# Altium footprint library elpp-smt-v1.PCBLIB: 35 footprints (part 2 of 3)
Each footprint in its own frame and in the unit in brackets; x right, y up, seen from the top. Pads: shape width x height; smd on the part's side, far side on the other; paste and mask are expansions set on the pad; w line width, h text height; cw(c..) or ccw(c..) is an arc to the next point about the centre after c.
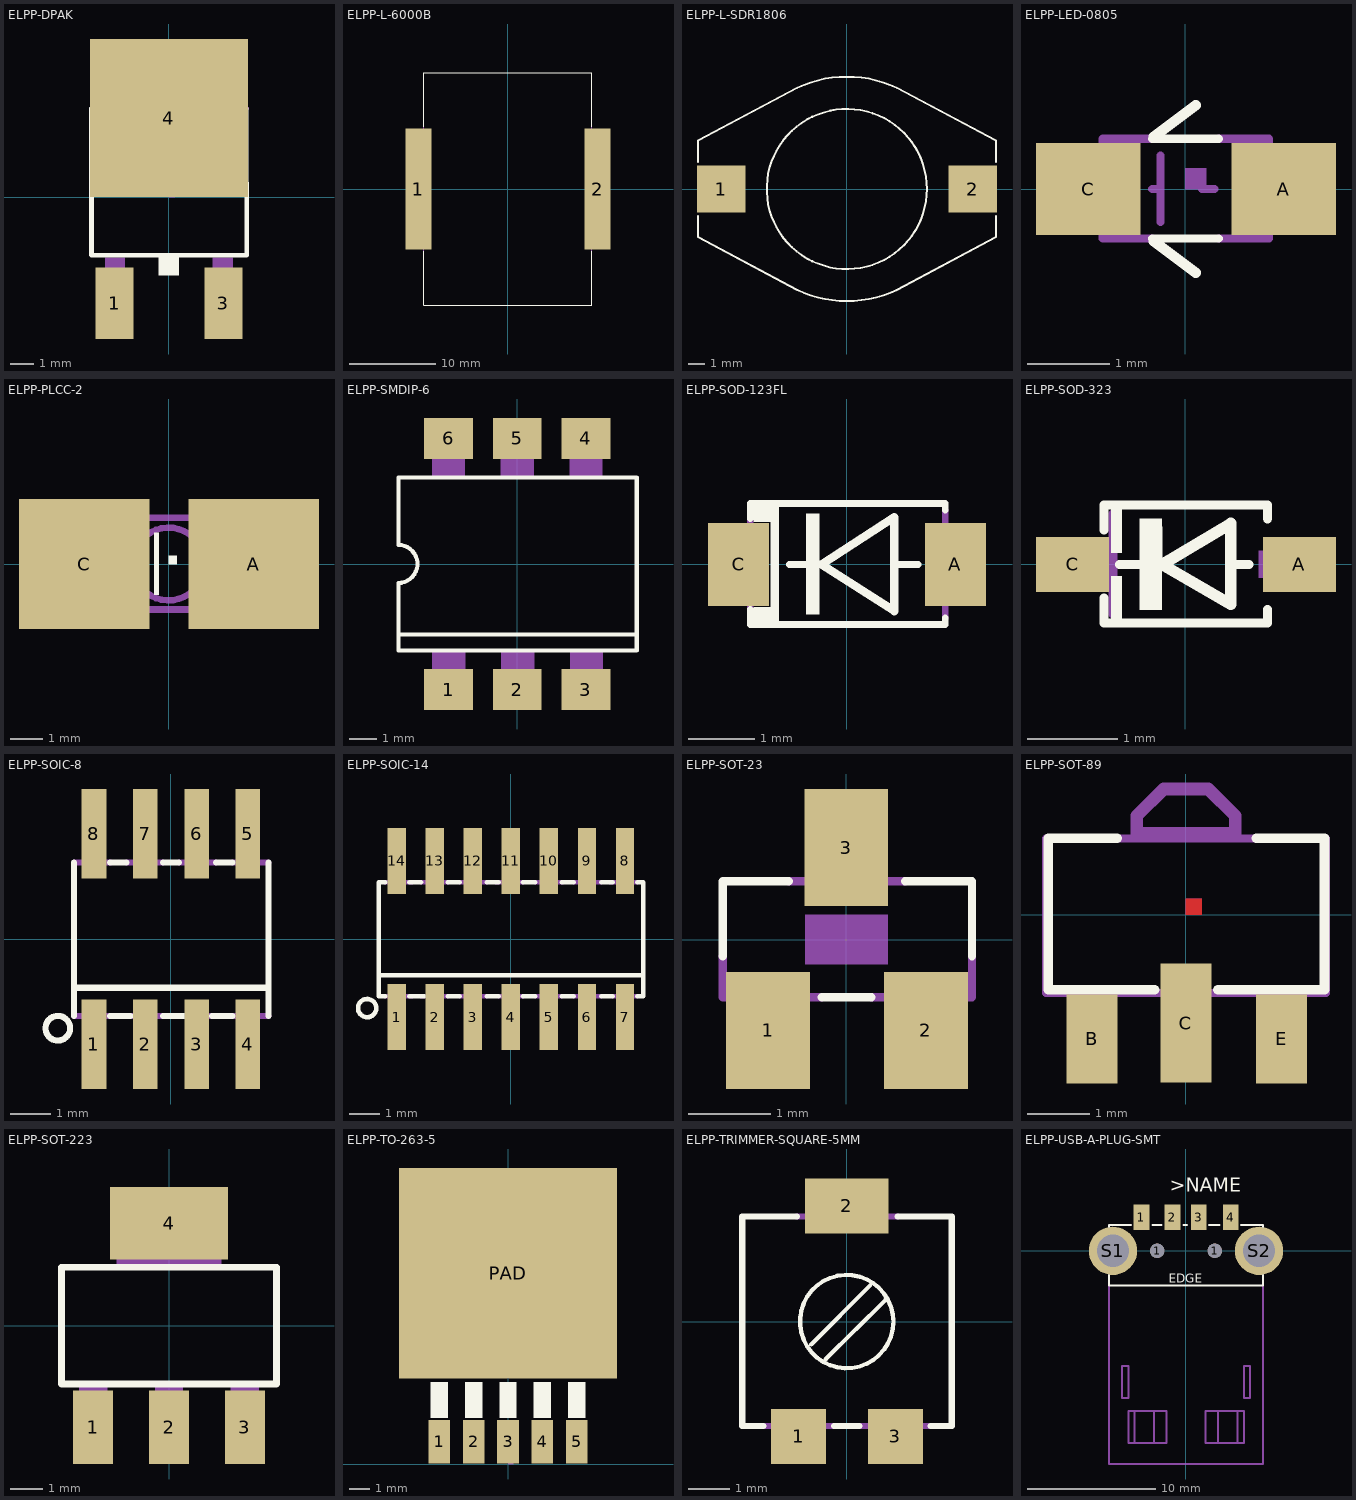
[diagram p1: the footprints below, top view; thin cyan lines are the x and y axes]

## ELPP-DPAK [mil]
pads (3):
  rect 63x119 smd: 1(-90.55,-177.17) 3(91,-177.17)
  rect 264x264 smd: 4(0,132)
Top Overlay:
  rectangle: -17,-130.81 17,-100.81
  lines w8: -129,148 -129.02,-96.81 130,-96.81 129,148
Mechanical 2:
  text ">NAME" at -150,-115.75 h42.5
Mechanical 4:
  text ">VALUE" at 200,-115.75 h42.5
Mechanical 16:
  rectangle: -107,-214.81 -73,-100.81
  rectangle: 73,-214.81 107,-100.81
  region: 0,0 10,0 10,10 0,10
  lines w8: -129.02,148 130,148 ; -101,152 -101,180 -83,198 83,198 101,180 101,152 -101,152

## ELPP-L-6000B [mil]
pads (2):
  rect 119x552 smd: 1(-409.45,0) 2(410,0)
Top Overlay:
  lines w5: -383.86,-283.46 -383.86,-531.5 384,-531.5 384,-283.46 ; -383.86,284 -383.86,532 384,532 384,284
Mechanical 2:
  text ">NAME" at -367.76,546 h42.5
Mechanical 4:
  text ">VALUE" at -364.96,452 h42.5
Mechanical 16:
  lines w5: -383.86,-283.46 -383.86,284 ; 384,-283.46 384,284

## ELPP-L-SDR1806 [mil]
pads (2):
  rect 119x115 smd: 1(-309.06,0) 2(310,0)
Top Overlay:
  circle w5: c0,0 r197
  lines w5: -366.14,-66.93 -366.14,-118.11 -122.05,-248.03 ccw(c-1.71,0.88) 0,-275.59 ccw(c2.29,2.47) 123,-248.03 367,-118.11 367,-66.93 ; -366.14,67 -366.14,119 -122.05,249 cw(c-3.01,0.27) 0,276 cw(c3.39,-2.24) 123,249 367,119 367,67
Mechanical 2:
  text ">NAME" at 243,204 h42.5
Mechanical 4:
  text ">VALUE" at 246,-253.54 h42.5

## ELPP-LED-0805 [mil]
pads (2):
  rect 50x44 smd: A(47,0) C(-46.26,0)
Top Overlay:
  lines w4: -15.75,-23.62 16,-23.62 ; -15.75,24 16,24
  lines w5: -15,-25 5,-40 ; -15,25 5,40
Mechanical 2:
  text ">NAME" at 77,-25.59 h42.5
Mechanical 4:
  text ">VALUE" at -61.02,-92.68 h42.5
Mechanical 16:
  region: 0,0 10,0 10,10 0,10
  lines w4: -15.75,-23.62 -39.37,-23.62 -39.37,24 -15.75,24 ; -15.75,0 -11.81,0 ; -11.81,-15.75 -11.81,0 ; -11.81,16 -11.81,0 ; 8,0 14,0 ; 16,-23.62 40,-23.62 40,24 16,24

## ELPP-PLCC-2 [mil]
pads (2):
  rect 158x158 smd: A(103,0) C(-102.36,0)
Top Overlay:
  rectangle: -17.72,-37.4 -11.81,38
  region: 0,0 10,0 10,10 0,10
Top Paste:
  region: -88.82,51.42 -88.82,-50.94 -29.29,-50.94 -29.29,51.42
  region: 29.74,51.74 29.74,-51.26 89.26,-51.26 89.26,51.74
Top Solder:
  rectangle: 24,-51.18 87,52
  region: -23.62,52 -86.61,52 -86.61,-51.18 -23.62,-51.18
Mechanical 2:
  text ">NAME" at 193,-22.05 h42.5
Mechanical 4:
  text ">VALUE" at -75,-150 h42.5
Mechanical 16:
  circle w8: c0,0 r44
  lines w4: -62.99,-43.31 -70.87,-43.31 -70.87,44 -62.99,44 ; 63,-43.31 71,-43.31 71,44 63,44
  lines w8: -62.99,34 -62.99,44 -62.99,56 -41.34,56 ; -62.99,34 -62.99,-43.31 -62.99,-55.12 63,-55.12 63,-43.31 63,44 63,56 -41.34,56 ; -62.99,34 -41.34,56

## ELPP-SMDIP-6 [mil]
pads (6):
  rect 71x60 smd: 1(-100,-182.87) 2(0,-182.87) 3(100,-182.87) 4(100,183) 5(0,183) 6(-100,183)
Top Overlay:
  lines w6: -173.23,-102.36 -173.23,-125.98 174,-125.98 174,-102.36 ; -173.23,-102.36 -173.23,-27.56 ccw(c-173.23,0.22) -173.23,28 -173.23,126 174,126 174,-102.36 ; -173.23,-102.36 174,-102.36
Mechanical 2:
  text ">NAME" at -200,-125 h42.5
Mechanical 4:
  text ">VALUE" at -114.57,-25 h42.5
Mechanical 16:
  rectangle: -123.82,-194.88 -75.59,-125.98
  rectangle: -23.82,-194.88 25,-125.98
  rectangle: 77,-194.88 125,-125.98
  region: 124,195 76,195 76,126 124,126
  region: 24,195 -24.41,195 -24.41,126 24,126
  region: -76.18,195 -124.41,195 -124.41,126 -76.18,126

## ELPP-SOD-123FL [mil]
pads (2):
  rect 36x49 smd: A(64,0) C(-63.98,0)
Top Overlay:
  rectangle: -24.15,-29.53 -16.28,30
  rectangle: -45,-35 -40,35
  rectangle: -55,25 -45,35
  rectangle: -55,-35 -45,-25
  lines w4: -57.09,-26.5 -57.09,-35.43 -54.59,-35.43 -52.09,-35.43 -49.59,-35.43 -47.09,-35.43 58,-35.43 58,-31.5 ; -57.09,27 -57.09,36 -54.59,36 -52.09,36 -49.59,36 -47.09,36 58,36 58,32 ; -34,0 -15,0 -13.78,0 ; 29,0 42,0
  lines w5: -15,0 28,28 28,-27.5 -15,0
Mechanical 2:
  text ">NAME" at 95,-23.62 h42.5
Mechanical 4:
  text ">VALUE" at -78.74,-98.43 h42.5
Mechanical 16:
  rectangle: -70.87,-21.65 -56.1,22
  region: 71,22 57,22 57,-21.65 71,-21.65
  lines w4: -57.09,-31.5 -57.09,32 ; 58,-31.5 58,32

## ELPP-SOD-323 [mil]
pads (2):
  rect 32x24 smd: A(50,0) C(-49.21,0)
Top Overlay:
  rectangle: -20,-20 -10,20
  rectangle: -32.5,-25 -27.5,-5
  rectangle: -32.5,5 -27.5,25
  lines w4: -35.43,-14.69 -35.43,-25.59 -32.93,-25.59 -30.43,-25.59 -27.93,-25.59 36,-25.59 36,-19.68 ; -35.43,15 -35.43,26 -32.93,26 -30.43,26 -27.93,26 36,26 36,20 ; -28.62,0 -11.81,0 -11.81,16 ; 20,0 28,0
  lines w5: -10,0 20,18 20,-17.5 -10,0
Mechanical 2:
  text ">NAME" at 73,-25.59 h42.5
Mechanical 4:
  text ">VALUE" at -64.96,-86.61 h42.5
Mechanical 16:
  rectangle: -49.21,-5.91 -31.5,6
  rectangle: 32,-5.91 50,6
  lines w4: -31.5,-21.65 -31.5,22

## ELPP-SOIC-8 [mil]
pads (8):
  rect 24x87 smd: 1(-75,-102.36) 2(-25,-102.36) 3(25,-102.36) 4(75,-102.36) 5(75,103) 6(25,103) 7(-25,103) 8(-75,103)
Top Overlay:
  circle w6: c-110.24,-86.61 r12
  lines w6: -94.49,-74.8 -94.49,75 ; -94.49,-47.24 95,-47.24 ; -59.06,-74.8 -39.37,-74.8 ; -59.06,75 -43.31,75 ; -7.87,-74.8 12,-74.8 ; -7.87,75 8,75 ; 40,-74.8 60,-74.8 ; 44,75 60,75 ; 95,-74.8 95,75
Mechanical 2:
  text ">NAME" at -125,-75 h42.5
Mechanical 4:
  text ">VALUE" at 175,-75 h42.5
Mechanical 16:
  rectangle: -84.65,-122.05 -65.35,-78.74
  rectangle: -34.65,-122.05 -15.35,-78.74
  rectangle: 16,-122.05 35,-78.74
  rectangle: 66,-122.05 85,-78.74
  rectangle: 66,79 85,123
  rectangle: 16,79 35,123
  rectangle: -34.65,79 -15.35,123
  rectangle: -84.65,79 -65.35,123
  lines w6: -94.49,-74.8 -59.06,-74.8 ; -94.49,75 -59.06,75 ; -43.31,75 -7.87,75 ; -39.37,-74.8 -7.87,-74.8 ; 8,-74.8 40,-74.8 ; 8,75 44,75 ; 60,-74.8 95,-74.8 ; 60,75 95,75

## ELPP-SOIC-14 [mil]
pads (14):
  rect 24x87 smd: 1(-150,-102.36) 2(-100,-102.36) 3(-50,-102.36) 4(0,-102.36) 5(50,-102.36) 6(100,-102.36) 7(150,-102.36) 8(150,103) 9(100,103) 10(50,103) 11(0,103) 12(-50,103) 13(-100,103) 14(-150,103)
Top Overlay:
  circle w6: c-188.98,-90.55 r12
  lines w6: -173.43,-74.8 -173.43,-47.24 ; -173.43,75 -173.43,-47.24 ; -173.23,-74.8 -165.35,-74.8 ; -173.23,75 -165.35,75 ; -133.86,-74.8 -114.17,-74.8 ; -133.86,75 -118.11,75 ; -82.68,-74.8 -66.93,-74.8 ; -82.68,75 -66.93,75 ; -31.5,-74.8 -15.75,-74.8 ; -31.5,75 -15.75,75 ; 16,-74.8 32,-74.8 ; 16,75 32,75 ; 67,-74.8 83,-74.8 ; 67,75 83,75 ; 119,-74.8 134,-74.8 ; 119,75 134,75 ; 166,-74.8 174,-74.8 174,-47.24 ; 166,75 174,75 174,-47.24 ; -173.43,-47.24 174,-47.24
Mechanical 2:
  text ">NAME" at -200,-75 h42.5
Mechanical 4:
  text ">VALUE" at 250,-75 h42.5
Mechanical 16:
  rectangle: -159.65,-122.05 -140.35,-78.74
  rectangle: -109.65,-122.05 -90.35,-78.74
  rectangle: -59.65,-122.05 -40.35,-78.74
  rectangle: -9.65,-122.05 10,-78.74
  rectangle: -9.65,79 10,123
  rectangle: -59.65,79 -40.35,123
  rectangle: -109.65,79 -90.35,123
  rectangle: -159.65,79 -140.35,123
  rectangle: 41,-122.05 60,-78.74
  rectangle: 91,-122.05 110,-78.74
  rectangle: 141,-122.05 160,-78.74
  rectangle: 141,79 160,123
  rectangle: 91,79 110,123
  rectangle: 41,79 60,123
  lines w6: -165.55,-74.8 -129.72,-74.8 ; -165.55,75 -129.72,75 ; -118.31,75 -82.48,75 ; -118.11,-74.8 -82.68,-74.8 ; -67.13,75 -31.3,75 ; -66.93,-74.8 -31.5,-74.8 ; -19.88,75 16,75 ; -15.75,-74.8 16,-74.8 ; 32,-74.8 67,-74.8 ; 32,75 68,75 ; 83,-74.8 119,-74.8 ; 83,75 119,75 ; 130,75 166,75 ; 134,-74.8 166,-74.8

## ELPP-SOT-23 [mil]
pads (3):
  rect 40x56 smd: 1(-37.4,-43.31) 2(38,-43.31) 3(0,44)
Top Overlay:
  lines w4: -59.06,-7.87 -59.06,28 -27.56,28 ; -11.81,-27.56 12,-27.56 ; 28,28 60,28 60,-7.87
Mechanical 2:
  text ">NAME" at 71,-23.43 h42.5
Mechanical 4:
  text ">VALUE" at 71,-81.69 h42.5
Mechanical 6:
  rectangle: -19.69,-11.81 20,12
Mechanical 16:
  rectangle: -9,28 9,51
  rectangle: 28,-51 46,-28
  rectangle: -46,-51 -28,-28
  lines w4: -59.06,-7.87 -59.06,-27.56 -11.81,-27.56 ; -27.56,28 28,28 ; 12,-27.56 60,-27.56 60,-7.87

## ELPP-SOT-89 [mil]
pads (3):
  rect 32x56 smd: B(-59.02,-77.99) E(60,-77.99)
  rect 32x75 smd: C(0,-67.99)
Top Layer:
  region: 0,0 10,0 10,10 0,10
Top Overlay:
  lines w6: -43.31,48 -86.61,48 -86.61,-47.24 -19.68,-47.24 ; 20,-47.24 87,-47.24 87,48 44,48
Top Paste:
  rectangle: -15.75,-105.51 16,-50.39
  region: 0,0 10,0 10,10 0,10
Top Solder:
  rectangle: -19.68,-109.45 20,-46.46
  region: 0,0 10,0 10,10 0,10
Mechanical 2:
  text ">NAME" at -56.69,129 h42.5
Mechanical 4:
  text ">VALUE" at -94.69,-171.06 h42.5
Mechanical 16:
  rectangle: -68,-83 -50,-50
  rectangle: 50,-83 68,-50
  rectangle: -11,-83 11,-50
  region: 0,0 10,0 10,10 0,10
  lines w5: -87.99,-49.02 88,-49.02 88,48 -87.99,48 -87.99,-49.02
  lines w8: -31,51 31,51 31,62 14,79 -14,79 -31,62 -31,51

## ELPP-SOT-223 [mil]
pads (4):
  rect 48x88 smd: 1(-91,-122) 2(0,-122) 3(91,-122)
  rect 142x87 smd: 4(0,123)
Top Overlay:
  lines w8: -129,-70 129,-70 129,70 -129,70 -129,-70
Mechanical 2:
  text ">NAME" at -64.57,176 h42.5
Mechanical 4:
  text ">VALUE" at 198,-155.12 h42.5
Mechanical 16:
  rectangle: -63,71 63,144
  rectangle: -17,-144 17,-71
  rectangle: -108,-144 -74,-71
  rectangle: 74,-144 108,-71
  rectangle: -63,71 63,144
  rectangle: -17,-144 17,-71
  rectangle: -108,-144 -74,-71
  rectangle: 74,-144 108,-71

## ELPP-TO-263-5 [mil]
pads (6):
  rect 42x85 smd: 1(-134,43) 2(-67,43) 3(0,43) 4(67,43) 5(134,43)
  rect 425x410 smd: PAD(0,372)
Top Overlay:
  rectangle: -17,90 17,160
  rectangle: 50,90 84,160
  rectangle: 117,90 151,160
  rectangle: -84,90 -50,160
  rectangle: -151,90 -117,160
Mechanical 2:
  text ">NAME" at -105.75,592 h42.5
Mechanical 4:
  text ">VALUE" at 277,170 h42.5
Mechanical 16:
  region: 0,0 10,0 10,10 0,10
  lines w8: -200,175 200,175 200,515 -200,515 -200,175 ; -196,517 -196,545 -178,563 178,563 196,545 196,517 -196,517

## ELPP-TRIMMER-SQUARE-5MM [mil]
pads (3):
  rect 52x52 smd: 1(-45.28,-108.27) 3(46,-108.27)
  rect 79x52 smd: 2(0,109)
Top Overlay:
  circle w4: c0,0 r44
  lines w4: -33.46,-21.65 22,34 ; -19.68,-35.43 36,20
  lines w6: -78.74,-98.43 -98.43,-98.43 -98.43,99 -47.24,99 ; -11.81,-98.43 12,-98.43 ; 48,99 99,99 99,-98.43 79,-98.43
Mechanical 2:
  text ">NAME" at -111.81,-98.03 h42.5
Mechanical 4:
  text ">VALUE" at 158,-117.72 h42.5
Mechanical 16:
  lines w6: -78.74,-98.43 -11.81,-98.43 ; -47.24,99 48,99 ; 12,-98.43 79,-98.43

## ELPP-USB-A-PLUG-SMT [mil]
pads (8):
  rect 48x79 smd: 1(-136.61,103) 2(-41.34,103) 3(39,103) 4(138,103)
  round 44 hole 44: 1(-88.58,0) 1(89,0)
  round 148.5 hole 99: S1(-224.41,0) S2(225,0)
Top Overlay:
  lines w6: -236.22,-59.06 -236.22,-106.3 237,-106.3 237,-59.06 ; -236.22,60 -236.22,79 -169.29,79 ; -102.36,79 -74.8,79 ; -7.87,79 4,79 ; 71,79 103,79 ; 170,79 237,79 237,60
  text "EDGE" at -53.15,-98.43 h27.2
  text ">NAME" at -49.21,182 h42.5
Mechanical 4:
  text ">VALUE" at 145,-151.81 h42.5
Mechanical 16:
  lines w6: -236.22,-106.3 -236.22,-655.51 237,-655.51 237,-106.3 ; -157.48,-590.55 -177.17,-590.55 -177.17,-492.13 -157.48,-492.13 ; -157.48,-590.55 -98.43,-590.55 ; -157.48,-590.55 -157.48,-492.13 ; -157.48,-492.13 -98.43,-492.13 ; -98.43,-590.55 -59.06,-590.55 -59.06,-492.13 -98.43,-492.13 ; -98.43,-590.55 -98.43,-492.13 ; 99,-590.55 60,-590.55 60,-492.13 99,-492.13 ; 99,-590.55 158,-590.55 ; 99,-590.55 99,-492.13 ; 99,-492.13 158,-492.13 ; 158,-590.55 178,-590.55 178,-492.13 158,-492.13 ; 158,-590.55 158,-492.13 ; -196.85,-452.76 -196.85,-354.33 -177.17,-354.33 -177.17,-452.76 -196.85,-452.76 ; 178,-452.76 178,-354.33 197,-354.33 197,-452.76 178,-452.76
